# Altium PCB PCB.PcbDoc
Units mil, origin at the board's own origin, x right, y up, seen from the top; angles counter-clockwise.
Board outline 2165.35 x 1771.65 mil, 4 copper layers (Top Layer, VCC, GND, Bottom Layer), stack 25.634 mil thick; 104 components, 82 nets, 409 pads, 177 vias.
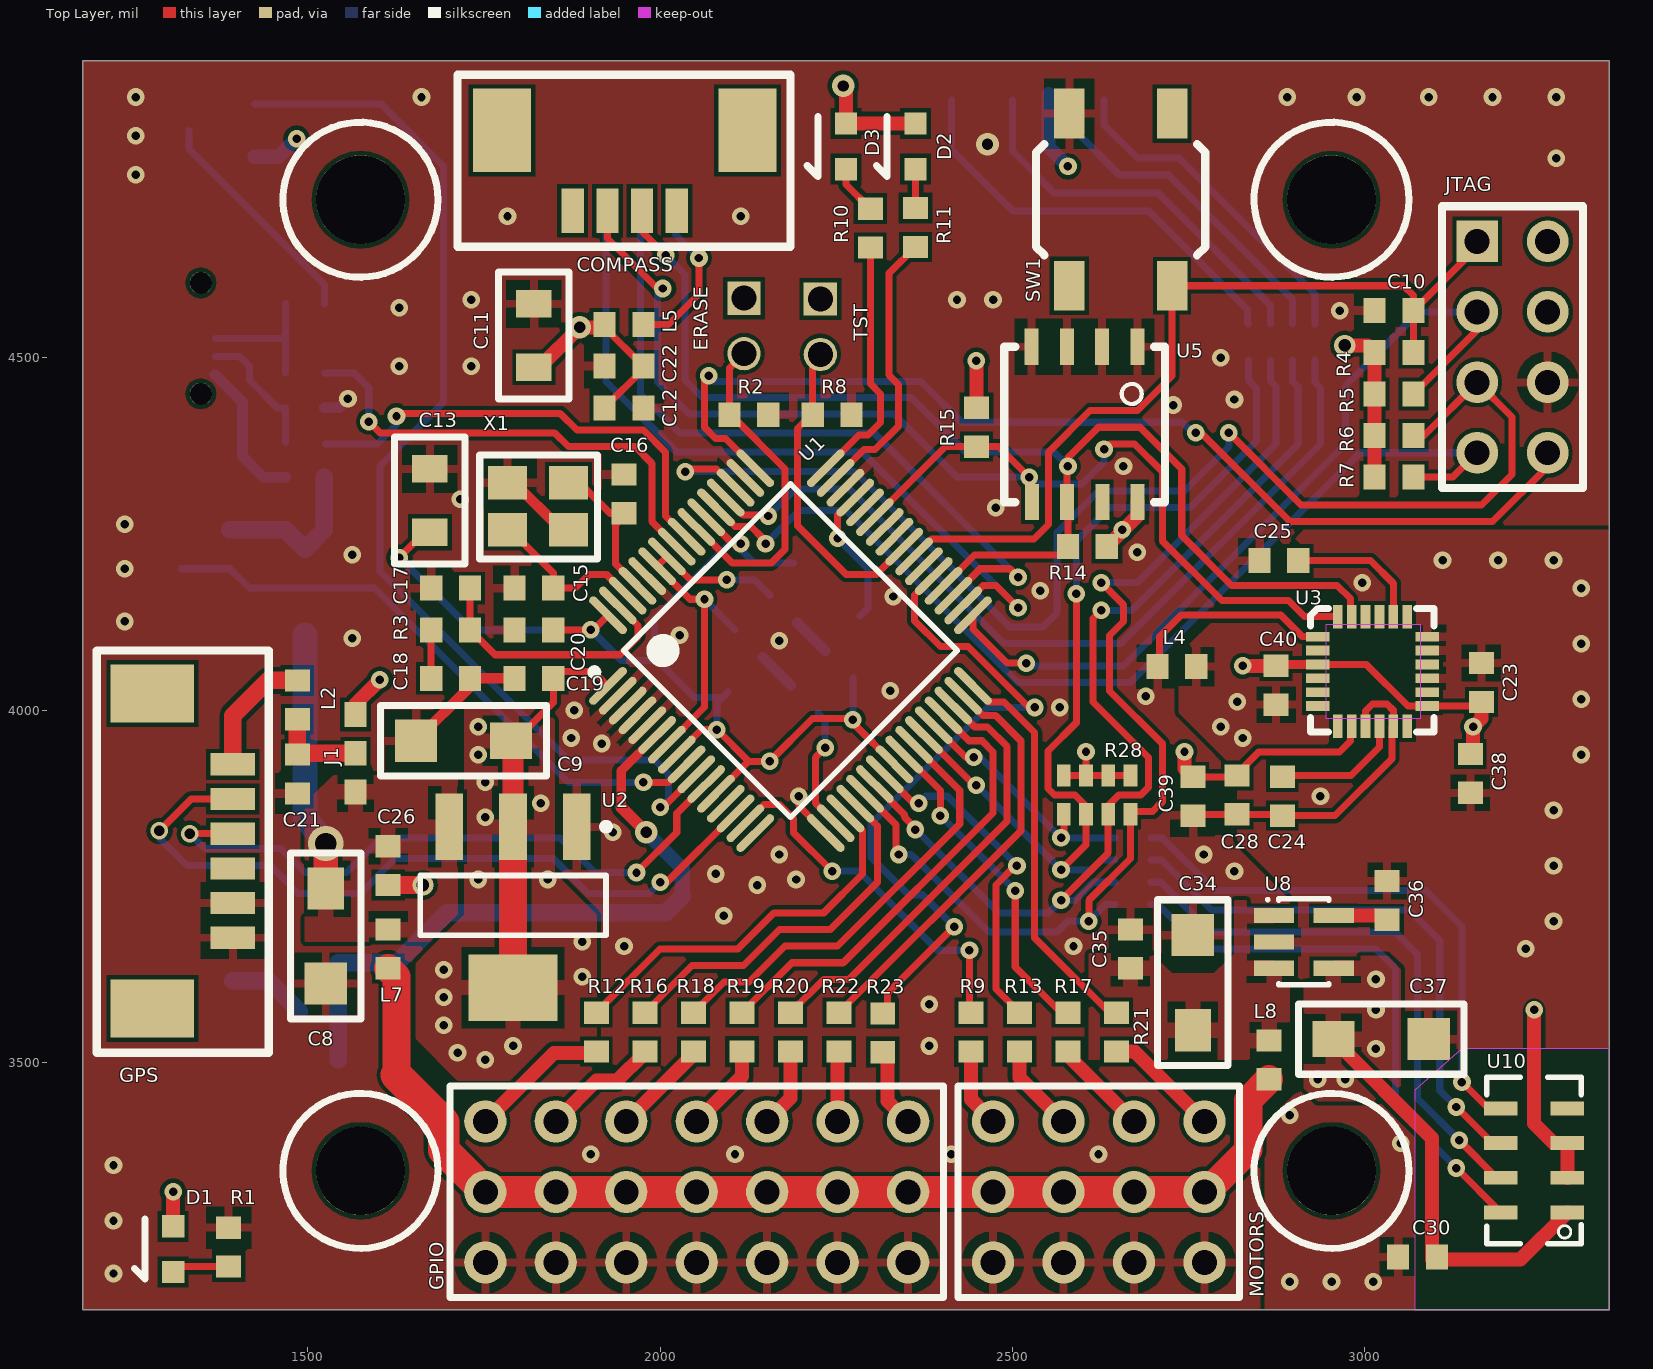
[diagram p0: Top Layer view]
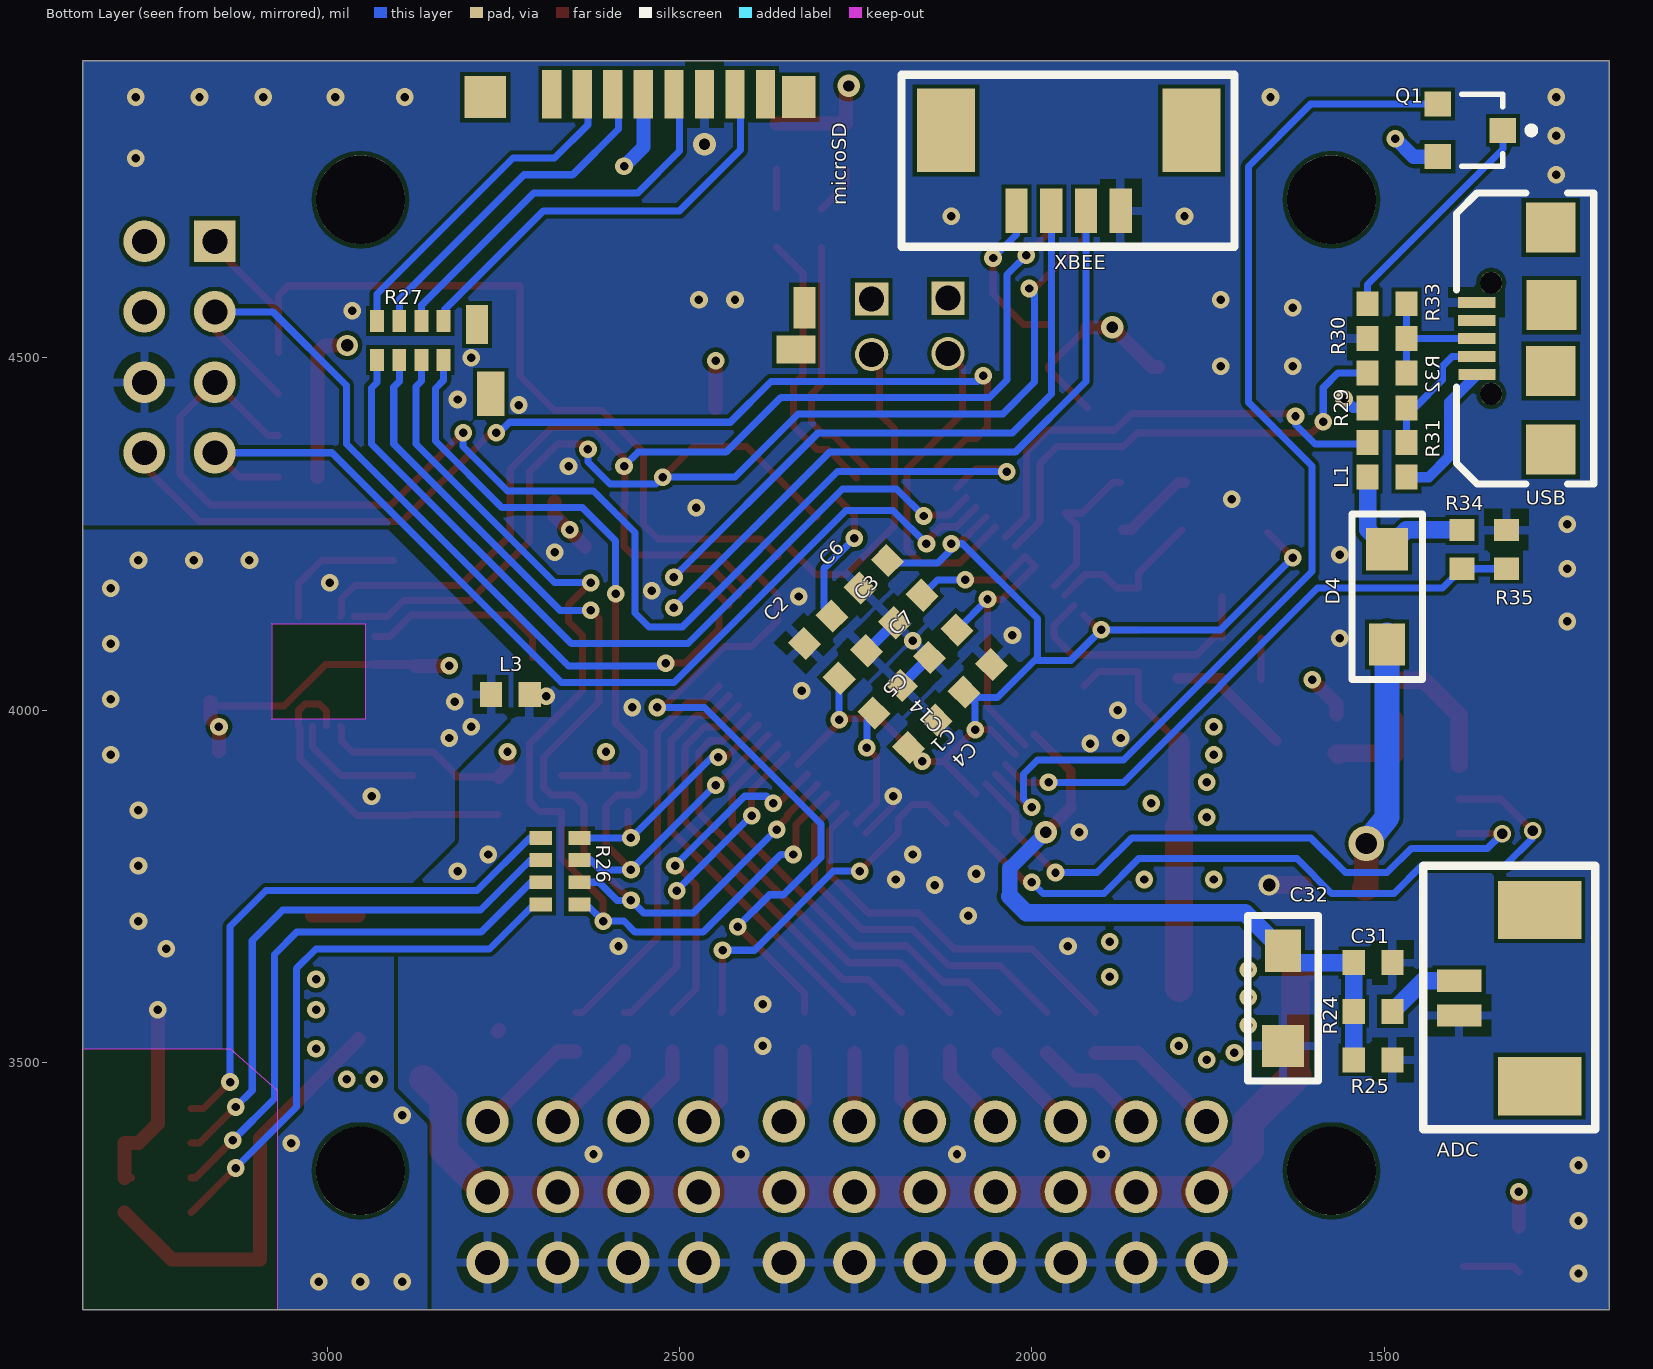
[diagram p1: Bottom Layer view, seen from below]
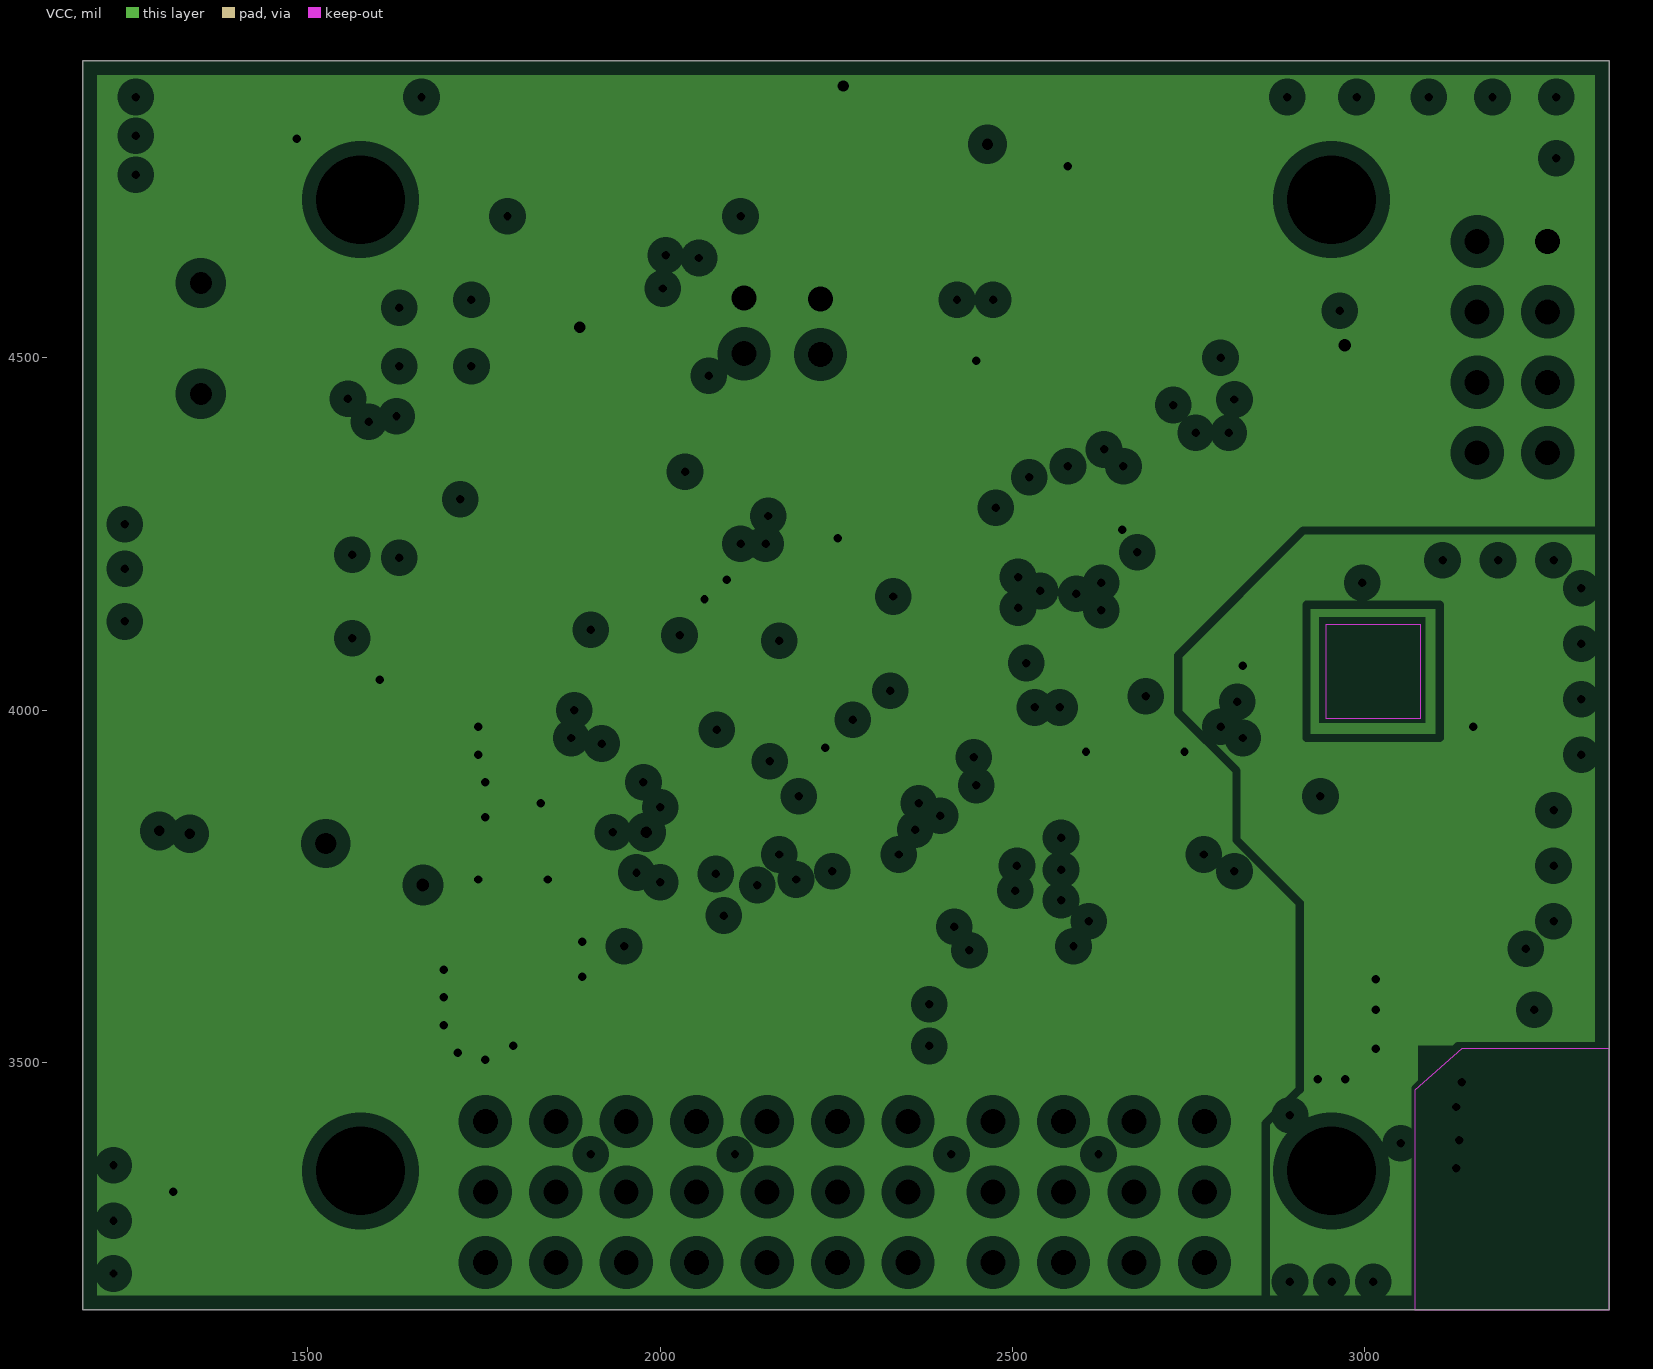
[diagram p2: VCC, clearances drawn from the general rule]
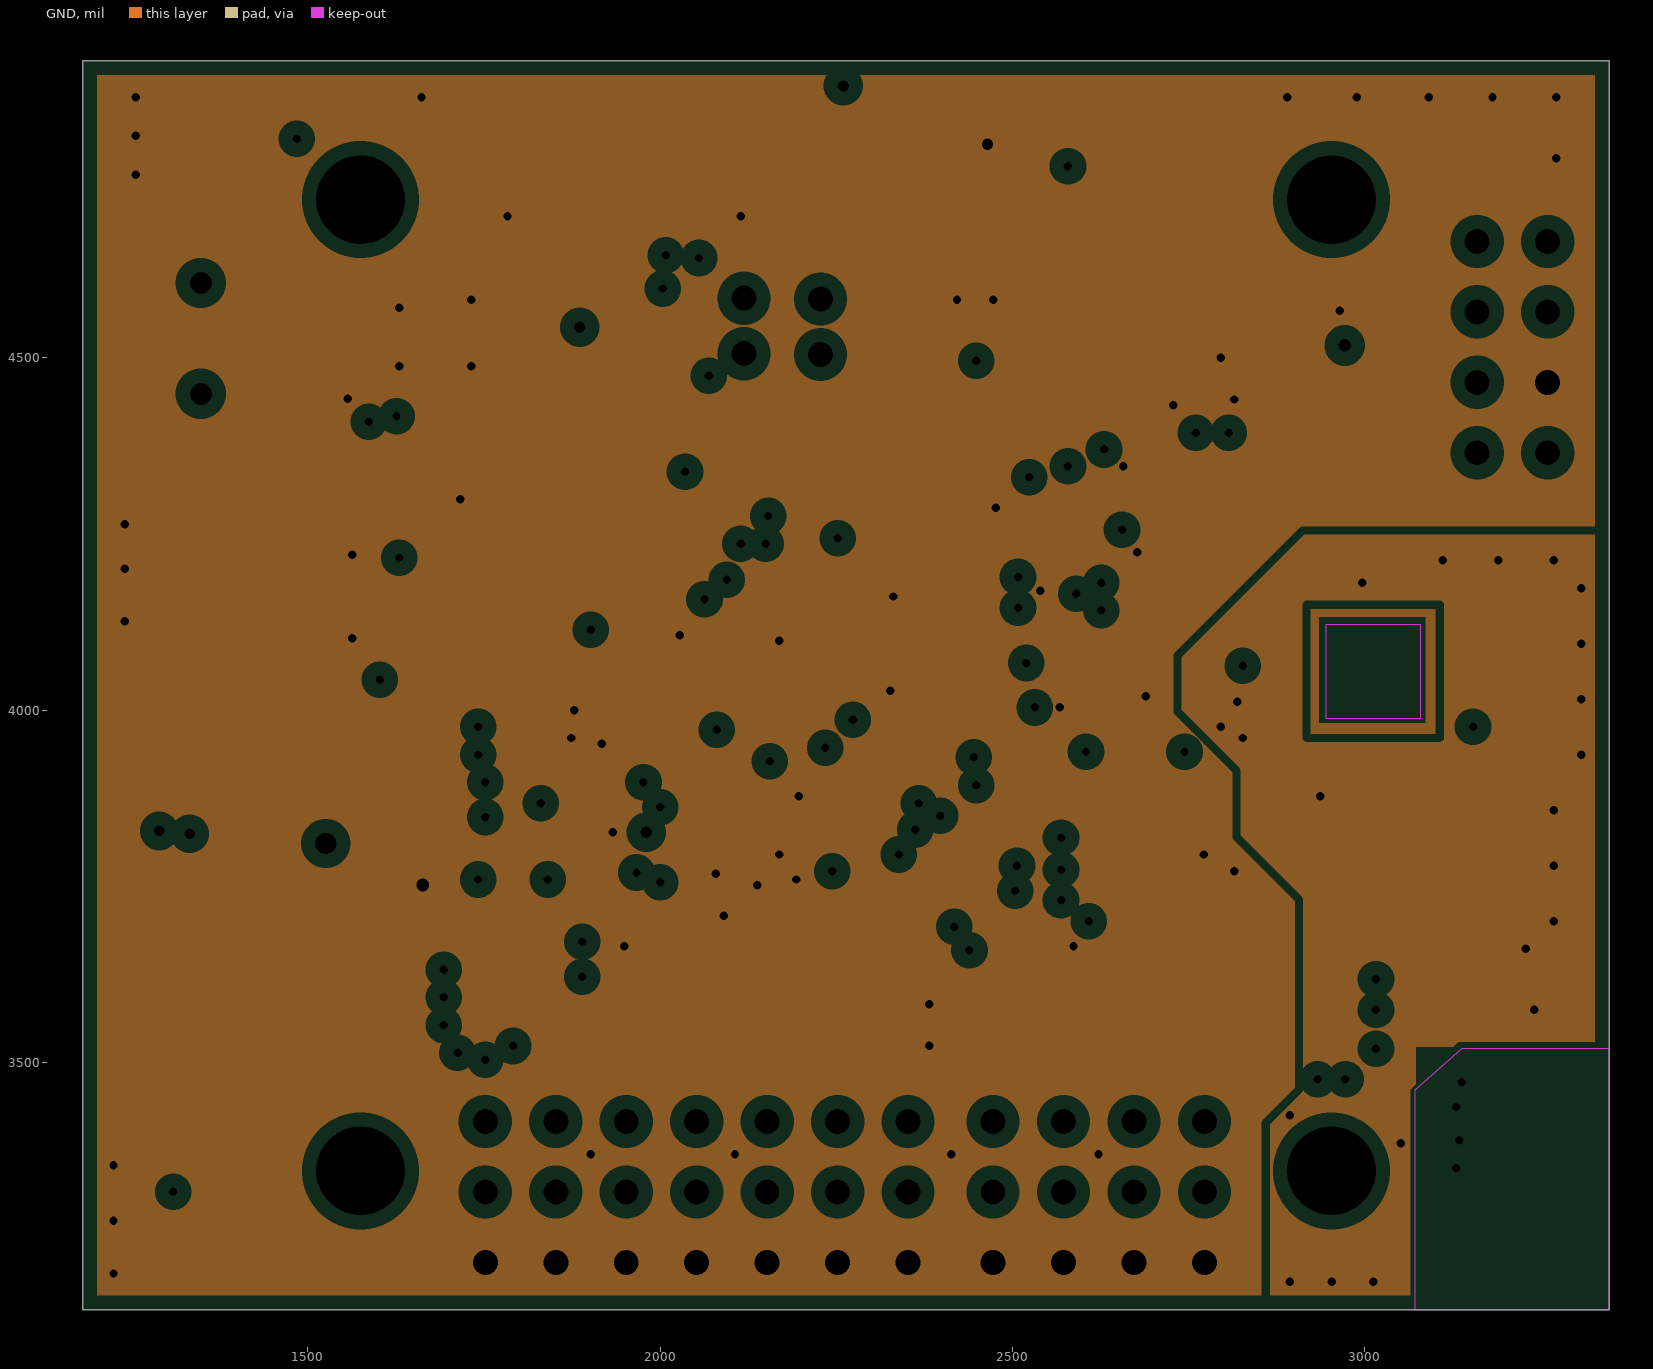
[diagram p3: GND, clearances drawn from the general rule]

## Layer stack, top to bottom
Top Solder: solder mask 0.4, Solder Resist, Dk 3.5
Top Layer: signal copper 1.4
Dielectric 1: core 5, FR-4, Dk 4.2
VCC: plane copper 1.417, net (Multiple Nets)
Dielectric 3: prepreg 5, Dk 4.2
GND: plane copper 1.417, net (Multiple Nets)
Dielectric 2: core 10, Dk 4.2
Bottom Layer: signal copper 1.4
Bottom Solder: solder mask 0.4, Solder Resist, Dk 3.5

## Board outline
1181.1,3149.61 3346.46,3149.61 3346.46,4921.26 1181.1,4921.26

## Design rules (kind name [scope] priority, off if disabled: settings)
Clearance [All] p1: gap=5.91
PlaneClearance [All] p1: clearance=20
PlaneConnect [All] p1: planeconnectstyle=Relief reliefexpansion=20 reliefentries=4 reliefconductorwidth=22 reliefairgap=10
PolygonConnect Via [IsVia] p1: connectstyle=Direct reliefconductorwidth=10 reliefentries=4 polygonreliefangle="90 Angle" airgapwidth=10
PolygonConnect Track [IsTrack] p2: connectstyle=Direct reliefconductorwidth=10 reliefentries=4 polygonreliefangle="90 Angle" airgapwidth=10
PolygonConnect GND [InNet('GND')] p3: connectstyle=Relief reliefconductorwidth=12 reliefentries=4 polygonreliefangle="90 Angle" airgapwidth=14
PolygonConnect AGND [InNet('AGND')] p4: connectstyle=Relief reliefconductorwidth=12 reliefentries=4 polygonreliefangle="90 Angle" airgapwidth=10
PolygonConnect A3V3 [InNet('A3V3')] p5: connectstyle=Relief reliefconductorwidth=22 reliefentries=4 polygonreliefangle="90 Angle" airgapwidth=10
PolygonConnect 5Vb [All] p6: connectstyle=Relief reliefconductorwidth=22 reliefentries=4 polygonreliefangle="90 Angle" airgapwidth=10
PolygonConnect 5Va [InNet('5VA')] p7: connectstyle=Relief reliefconductorwidth=22 reliefentries=4 polygonreliefangle="90 Angle" airgapwidth=10
PolygonConnect 3.3V [InNet('3.3V')] p8: connectstyle=Relief reliefconductorwidth=22 reliefentries=4 polygonreliefangle="90 Angle" airgapwidth=10
RoutingVias [All] p1: holewidth=28 width=50 viastyle="Through Hole" minholewidth=28 minwidth=50 maxholewidth=28 maxwidth=50
SolderMaskExpansion [All] p1: expansion=4
Width [All] p1: maxlimit=100 minlimit=10 preferedwidth=10
27 further rules are at their usual default settings.

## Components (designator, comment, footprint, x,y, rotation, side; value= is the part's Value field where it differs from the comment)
ADC "AD_Port" 2P_1.25mm（贴片） 1220.47,3425.2 r90 bottom
C1 "0.1u" 1608[0603] 2204.72,4015.75 r315 bottom
C2 "0.1u" 1608[0603] 2303.15,4114.17 r135 bottom
C3 "0.1u" 1608[0603] 2175.2,4143.7 r135 bottom
C4 "0.1u" 1608[0603] 2155.51,3966.54 r315 bottom
C5 "0.1u" 1608[0603] 2253.94,4064.96 r315 bottom
C6 "0.1u" 1608[0603] 2224.41,4192.91 r135 bottom
C7 "0.1u" 1608[0603] 2125.98,4094.49 r135 bottom
C8 "10u" 1206 1525.59,3612.2 r90 top
C9 "10u" 1206 1653.54,3956.69 r0 top
C10 "0.01u" 1608[0603] 3041.34,4566.93 r0 top
C11 "2.2u" 0805 1820.87,4576.77 r270 top
C12 "1n" 1608[0603] 1948.82,4429.13 r180 top
C13 "4.7u" 0805 1673.23,4342.52 r270 top
C14 "0.1u" 1608[0603] 2076.77,4045.28 r315 bottom
C15 "8p" 1608[0603] 1820.87,4173.23 r0 top
C16 "8p" 1608[0603] 1948.82,4307.09 r270 top
C17 "1n" 1608[0603] 1702.76,4173.23 r0 top
C18 "10n" 1608[0603] 1702.76,4045.28 r180 top
C19 "0.1u" 1608[0603] 1820.87,4045.28 r0 top
C20 "0.1u" 1608[0603] 1820.87,4114.17 r0 top
C21 "1u" 1608[0603] 1485.24,3909.45 r90 top
C22 "1u" 1608[0603] 1948.82,4488.19 r0 top
C23 "0.1u" 1608[0603] 3165.35,4039.37 r270 top
C24 "0.1u" 1608[0603] 2882.87,3877.95 r90 top
C25 "2.2n" 1608[0603] 2877.95,4212.6 r0 top
C26 "0.1u" 1608[0603] 1614.17,3779.53 r90 top
C28 "10n" 1608[0603] 2818.9,3879.92 r90 top
C30 "0.1u" 1608[0603] 3074.8,3224.41 r0 top
C31 "0.1u" 1608[0603] 1515.75,3641.73 r0 bottom
C32 "10u" 1206 1643.7,3523.62 r90 bottom
C34 "10u" 1206 2755.91,3681.1 r270 top
C35 "0.1u" 1608[0603] 2667.32,3661.42 r270 top
C36 "470p" 1608[0603] 3031.5,3730.32 r270 top
C37 "10u" 1206 3090.55,3533.46 r180 top
C38 "2.2u" 1608[0603] 3149.61,3910.43 r90 top
C39 "1u" 1608[0603] 2755.91,3877.95 r90 top
C40 "0.1u" 1608[0603] 2874.02,4035.43 r90 top
COMPASS "COMPASS" 4P_1.25mm（贴片） 2165.35,4881.89 r180 top
D1 "LED" LED 1309.06,3267.72 r270 top
D2 "LED" LED 2263.78,4832.68 r270 top
D3 "LED" LED 2362.2,4832.68 r270 top
D4 "Diode" 1206 1496.06,4228.35 r270 bottom
ERASE "MHDR1X2" PIN2mm*2 2119.09,4584.65 r270 top
GPIO "3*7 PWMin" HEADER3X7 1751.97,3216.54 r0 top
GPS "GPS" 6P_PH1.25mm（贴片） 1220.47,4064.96 r270 top
J1 "0603Jumper" 1-2Jumper 1567.91,3938.98 r270 top
JTAG "JTAG" JTAG2 3159.45,4665.35 r0 top
L1 "Ferrite" 1608[0603] 1496.06,4330.71 r0 bottom
L2 "Ferrite" 1608[0603] 1485.24,4014.76 r270 top
L3 "Ferrite" 1608[0603] 2740.16,4022.64 r0 bottom
L4 "Ferrite" 1608[0603] 2733.27,4062.01 r0 top
L5 "Ferrite" 1608[0603] 1948.82,4547.24 r180 top
L7 "" 1608[0603] 1614.17,3661.42 r90 top
L8 "" 1608[0603] 2864.17,3503.94 r90 top
microSD "SD Connector" SD_Connector 2377.95,4838.58 r0 bottom
MOTORS "3*4P PWMout" header3x4 2472.44,3216.54 r0 top
Q1 "ZXM61P02F" SOT23 1377.95,4822.83 r270 bottom
R1 "1K" 1608[0603] 1387.8,3238.19 r270 top
R2 "10K" 1608[0603] 2125.98,4419.29 r180 top
R3 "1.5K" 1608[0603] 1702.76,4114.17 r0 top
R4 "47K" 1608[0603] 3041.34,4507.87 r180 top
R5 "10K" 1608[0603] 3041.34,4448.82 r180 top
R6 "10K" 1608[0603] 3041.34,4389.76 r180 top
R7 "10K" 1608[0603] 3041.34,4330.71 r180 top
R8 "10K" 1608[0603] 2244.09,4419.29 r180 top
R9 "1K" 1608[0603] 2440.94,3543.31 r270 top
R10 "270R" 1608[0603] 2298.23,4684.06 r90 top
R11 "270R" 1608[0603] 2362.2,4685.04 r90 top
R12 "220" 1608[0603] 1909.45,3543.31 r270 top
R13 "1K" 1608[0603] 2509.84,3543.31 r270 top
R14 "47K" 1608[0603] 2606.3,4232.28 r180 top
R15 "47K" 1608[0603] 2448.82,4401.57 r270 top
R16 "220" 1608[0603] 1978.35,3543.31 r270 top
R17 "1K" 1608[0603] 2578.74,3543.31 r270 top
R18 "220" 1608[0603] 2047.24,3543.31 r270 top
R19 "220" 1608[0603] 2116.14,3543.31 r270 top
R20 "220" 1608[0603] 2185.04,3543.31 r270 top
R21 "1K" 1608[0603] 2647.64,3543.31 r270 top
R22 "220" 1608[0603] 2253.94,3543.31 r270 top
R23 "220" 1608[0603] 2315.94,3542.32 r270 top
R24 "200K" 1608[0603] 1515.75,3572.83 r180 bottom
R25 "470K" 1608[0603] 1515.75,3503.94 r0 bottom
R26 "100R*4" Resistances 2696.85,3818.9 r270 bottom
R27 "100R*4" Resistances 2929.13,4497.05 r180 bottom
R28 "47K*4" Resistances 2667.32,3907.48 r180 top
R29 "330K" 1608[0603] 1496.06,4429.13 r0 bottom
R30 "330K" 1608[0603] 1496.06,4527.56 r0 bottom
R31 "22R" 1608[0603] 1496.06,4379.92 r0 bottom
R32 "22R" 1608[0603] 1496.06,4478.35 r0 bottom
R33 "1.5K" 1608[0603] 1496.06,4576.77 r180 bottom
R34 "27K" 1608[0603] 1389.76,4228.35 r270 bottom
R35 "47K" 1608[0603] 1326.77,4228.35 r270 bottom
SW1 "Push Button" switch 2746.06,4566.93 r90 top
TST "MHDR1X2" PIN2mm*2 2227.36,4583.66 r270 top
U1 "AT91SAM7S256-AU-001" LQFP64_N 2185.04,4084.65 r45 top
U2 "LM1117N33" SOT230P700X180-4N 1791.34,3720.47 r270 top
U3 "MPU9150" LGANEW 2933.07,4104.33 r0 top
U5 "EEPROM" EEPROM 2677.17,4515.75 r180 top
U8 "MIC5207LE33" S5 2913.39,3671.26 r270 top
U10 "MS5611" MS_5611 3287.4,3287.4 r180 top
USB "USB_Receptacle" micro_usb 1348.43,4606.3 r0 bottom
X1 "" OSC2 1783.46,4322.83 r0 top
XBEE "XBEE" 4P_1.25mm（贴片） 1732.28,4881.89 r0 bottom

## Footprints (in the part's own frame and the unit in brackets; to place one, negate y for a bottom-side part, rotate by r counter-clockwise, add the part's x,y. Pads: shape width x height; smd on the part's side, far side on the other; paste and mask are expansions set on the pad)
1-2Jumper [mm]
  rect 0.9x0.8 smd: 1(0,0) 2(1.4,0) 3(-1.4,0)
2P_1.25mm（贴片） [mm]
  rect 2.1x3 smd: 0(1.05,1.5) 5(7.4,1.5)
  rect 0.8x1.6 smd: 1(4.85,4.4) 2(3.6,4.4)
  silkscreen extent -0.5,-0.5 9,5.7
4P_1.25mm（贴片） [mm]
  rect 2.1x3 smd: 0(1.05,1.5) 5(9.9,1.5)
  rect 0.8x1.6 smd: 1(7.35,4.4) 2(6.1,4.4) 3(4.85,4.4) 4(3.6,4.4)
  silkscreen extent -0.5,-0.5 11.5,5.7
6P_PH1.25mm（贴片） [mm]
  rect 2.1x3 smd: 0(1.05,1.5) 7(12.4,1.5)
  rect 0.8x1.6 smd: 1(3.6,4.4) 2(4.85,4.4) 3(6.1,4.4) 4(8.6,4.4) 4(9.85,4.4) 5(7.35,4.4)
  silkscreen extent -0.5,-0.5 14,5.7
0805 [mm]
  rect 1x1.27 smd: 1(0,0) 2(2.286,0)
  silkscreen extent -1.14,-1.27 3.43,1.27
1206 [mil]
  rect 60x60 smd: 1(0,0)
  rect 60x51.18 smd: 2(135,0)
  silkscreen extent -50,-50 185,50
1608[0603] [mm] "Chip Capacitor, Body 1.6x0.8mm, IPC High Density"
  rect 0.8x0.9 smd: 1(-0.7,0) 2(0.7,0)
  body extent -0.87,-0.47 0.87,0.47, height 1.3
EEPROM [mm]
  rect 0.5x1.3 smd: 1(0,0) 2(1.27,0) 3(2.54,0) 4(3.81,0) 5(3.8,5.6) 6(2.53,5.6) 7(1.26,5.6) 8(-0.01,5.6)
  silkscreen extent -1,0 4.8,5.6
header3x4 [mil]
  round 60 hole 35.43: 1(0,0) 2(0,100) 3(0,200) 4(100,0) 5(100,100) 6(100,200) 7(200,0) 8(200,100) 9(200,200) 10(300,0) 11(300,100) 12(300,200)
  silkscreen extent -50,-50 350,250
HEADER3X7 [mil]
  round 60 hole 35.43: 1(0,0) 2(0,100) 3(0,200) 4(100,0) 5(100,100) 6(100,200) 7(200,0) 8(200,100) 9(200,200) 10(300,0) 11(300,100) 12(300,200) 13(400,0) 14(400,100) 15(400,200) 16(500,0) 17(500,100) 18(500,200) 19(600,0) 20(600,100) 21(600,200)
  silkscreen extent -50,-50 650,250
JTAG2 [mm]
  rect 1.5x1.5 hole 0.9: 1(0,0)
  round 1.5 hole 0.9: 2(0,-2.54) 3(0,-5.08) 4(0,-7.62) 5(2.54,0) 6(2.54,-2.54) 7(2.54,-5.08) 8(2.54,-7.62)
  silkscreen extent -1.27,-8.89 3.81,1.27
LED [mm]
  rect 0.8x0.8 smd: 1(0,0) 2(1.65,0)
  silkscreen extent -0.25,-1.4 1.9,-1.02
LGANEW [mm]
  rect 0.85x0.35 smd mask+0: 1(0,0) 2(0,-0.5) 3(0,-1) 4(0,-1.5) 5(0,-2) 6(0,-2.5) 13(3.95,-2.5) 14(3.95,-2) 15(3.95,-1.5) 16(3.95,-1) 17(3.95,-0.5) 18(3.95,0)
  rect 0.35x0.85 smd mask+0: 7(0.725,-3.225) 8(1.225,-3.225) 9(1.725,-3.225) 10(2.225,-3.225) 11(2.725,-3.225) 12(3.225,-3.225) 19(3.225,0.725) 20(2.725,0.725) 21(2.225,0.725) 22(1.725,0.725) 23(1.225,0.725) 24(0.725,0.725)
  silkscreen extent -0.25,-3.43 4.19,1.02
LQFP64_N [mm] "Thin QFP, 64-Leads, Body 10x10mm, Pitch 0.5mm, IPC Medium Density"
  oval 1.8x0.3 smd: 1(-5.55,3.75) 2(-5.55,3.25) 3(-5.55,2.75) 4(-5.55,2.25) 5(-5.55,1.75) 6(-5.55,1.25) 7(-5.55,0.75) 8(-5.55,0.25) 9(-5.55,-0.25) 10(-5.55,-0.75) 11(-5.55,-1.25) 12(-5.55,-1.75) 13(-5.55,-2.25) 14(-5.55,-2.75) 15(-5.55,-3.25) 16(-5.55,-3.75) 33(5.55,-3.75) 34(5.55,-3.25) 35(5.55,-2.75) 36(5.55,-2.25) 37(5.55,-1.75) 38(5.55,-1.25) 39(5.55,-0.75) 40(5.55,-0.25) 41(5.55,0.25) 42(5.55,0.75) 43(5.55,1.25) 44(5.55,1.75) 45(5.55,2.25) 46(5.55,2.75) 47(5.55,3.25) 48(5.55,3.75)
  oval 0.3x1.8 smd: 17(-3.75,-5.55) 18(-3.25,-5.55) 19(-2.75,-5.55) 20(-2.25,-5.55) 21(-1.75,-5.55) 22(-1.25,-5.55) 23(-0.75,-5.55) 24(-0.25,-5.55) 25(0.25,-5.55) 26(0.75,-5.55) 27(1.25,-5.55) 28(1.75,-5.55) 29(2.25,-5.55) 30(2.75,-5.55) 31(3.25,-5.55) 32(3.75,-5.55) 49(3.75,5.55) 50(3.25,5.55) 51(2.75,5.55) 52(2.25,5.55) 53(1.75,5.55) 54(1.25,5.55) 55(0.75,5.55) 56(0.25,5.55) 57(-0.25,5.55) 58(-0.75,5.55) 59(-1.25,5.55) 60(-1.75,5.55) 61(-2.25,5.55) 62(-2.75,5.55) 63(-3.25,5.55) 64(-3.75,5.55)
  silkscreen extent -5.67,-4.25 4.25,4.57, body extent -5,-5 5,5, height 1.6
micro_usb [mm]
  rect 1.35x0.4 smd: 1(0.508,3.302) 2(0.525,2.65) 3(0.525,2) 4(0.525,1.35) 5(0.525,0.7)
  rect 1.8x1.8 smd: 6(-2.175,0.8) 6(-2.15,-2) 6(-2.15,3.175) 6(-2.15,6)
  round 0.8 hole 0.8: 18(0,0) 19(0,4)
  silkscreen extent -3.7,-3.25 1.25,7.25
MS_5611 [mm]
  rect 1.2x0.5 smd: 1(0,0) 2(0,-1.25) 3(0,-2.5) 4(0,-3.75) 5(2.4,-3.75) 6(2.4,-2.5) 7(2.4,-1.25) 8(2.4,0)
  silkscreen extent -0.5,-4.88 2.9,1.13
OSC2 [mm]
  rect 1.4x1.2 smd: 1(0,-1.7) 2(2.2,-1.7) 3(2.2,0) 4(0,0)
  silkscreen extent -1,-2.75 3.25,1
PIN2mm*2 [mm]
  rect 1.2x1.2 hole 0.9: 1(0,0)
  round 1.2 hole 0.9: 2(2,0)
Resistances [mm]
  rect 0.5x0.8 smd: 1(0,0) 2(0.8,0) 3(1.6,0) 4(2.4,0) 5(2.4,1.4) 6(1.6,1.4) 7(0.8,1.4) 8(0,1.4)
S5 [mm] "SOT-23/SC-74A; 5 Leads; Body 3.1 x 3 mm, inc. leads (LxW max)"
  rect 0.55x1.45 smd: 1(-0.95,-1.075) 2(0,-1.075) 3(0.95,-1.075) 4(0.95,1.075) 5(-0.95,1.075)
  silkscreen extent -1.57,-1.35 1.55,0.9
SD_Connector [mm]
  rect 0.7x1.75 smd: 1(6.6,-0.9) 2(5.5,-0.9) 3(4.4,-0.9) 4(3.3,-0.9) 5(2.2,-0.9) 6(1.1,-0.9) 7(0,-0.9) 7(7.7,-0.9)
  rect 0.8x1.5 smd: 7(-1.4,6.8)
  rect 1.2x1.5 smd: 7(-1.2,-0.8)
  rect 1.4x1 smd: 7(-1.1,8.3)
  rect 1x1.6 smd: 7(9.9,9.9)
  rect 1.5x1.5 smd: 7(10.1,-0.8)
  rect 0.8x1.4 smd: 7(10.4,7.4)
SOT23 [mm] "SOT-23; 3 Leads; Body 3.1 x 2.5 mm, inc. leads (LxW max), Alternate Lead Configuration"
  rect 0.9x0.95 smd: 1(0,1.175) 2(0.95,-1.175) 3(-0.95,-1.175)
  silkscreen extent -1.3,-0.3 1.3,2.32
SOT230P700X180-4N [mm] "SOT223, 4-Leads, Body 6.50x7.00mm (avg), Pitch 2.30mm, IPC Medium Density"
  rect 2.4x1 smd: 1(-2.9,2.3) 2(-2.9,0) 3(-2.9,-2.3)
  rect 2.4x3.2 smd: 4(2.9,0)
  silkscreen extent -3.02,-3.35 1.02,3.48, body extent -1.85,-3.35 1.85,3.35, height 1.8
switch [mm]
  rect 1.8x1.1 smd: 1(0.9,4.2) 2(7.1,4.2) 3(0.9,0.5) 4(7.1,0.5)
  silkscreen extent 2,-0.7 6,5.4

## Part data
C1 C2 C3 C4 C5 C6 C7 C10 C12 C14 C15 C16 C17 C18 C19 C20 C21 C22 C23 C24 C25 C28 C30 C31 C35 C36 C37 C38 C39 C40: library part "Cap 0603", "0603 Capacitor"
C8 C9 C26 C32 C34: library part "Cap 1206", "1206 Capacitor"
C11 C13: library part "Cap 0805", "0805 Capacitor"
COMPASS GPS XBEE: "Header, 4-Pin"
D1 D2 D3: "Typical RED, GREEN, YELLOW, AMBER GaAs LED"
D4: "Default Diode"
ERASE TST: "Header, 2-Pin"
GPIO: library part MyPWMin
JTAG: library part JTAG2
L1 L3 L4 L7 L8: library part Inductor, "Inductor"
MOTORS: library part MyPWMout
Q1: "20V P-Channel Enhancement Mode MOSFET"
R1 R2 R3 R4 R5 R6 R7 R8 R9 R10 R11 R12 R13 R14 R15 R16 R17 R18 R19 R20 R21 R22 R23 R24 R25 R29 R30 R31 R32 R33 R34 R35: library part "Res 0603", "Resistor"
R26 R27 R28: library part "Res Pack4", "Isolated Resistor Network"
U1: "AT91 ARM Thumb-based 32-bit Microcontroller, 256KB Flash, 64KB SRAM, 64-Pin LQFP, 11-ch. PDC, Industrial Grade (-40癈 to 85癈), Pb-Free"
U2: library part LM1117S33, "3.3V Regulator"
U5: library part ROM
U8: library part MIC5207
X1: library part OSC2

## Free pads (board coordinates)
  round 125.98 hole 125.98: 0(1574.8,3346.46) 1(2952.76,3346.46) 2(2952.76,4724.41) 3(1574.8,4724.41)

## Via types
v1: diameter 25, hole 12, Top Layer to Bottom Layer, 168 vias
v2: diameter 32, hole 16, Top Layer to Bottom Layer, 4 vias
v3: diameter 30, hole 18, Top Layer to Bottom Layer, 2 vias
v4: diameter 25, hole 15, Top Layer to Bottom Layer, 2 vias
v5: diameter 50, hole 30, Top Layer to Bottom Layer, 1 vias

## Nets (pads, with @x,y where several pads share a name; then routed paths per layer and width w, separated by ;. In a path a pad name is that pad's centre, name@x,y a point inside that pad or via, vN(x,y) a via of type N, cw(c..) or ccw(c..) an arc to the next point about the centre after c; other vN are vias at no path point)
3.3V: C1.2 C2.2 C3.2 C7.2 C9.2 C11.2 C12.2 C19.2 C22.2 C28.2 C39.2 D1.1 D2.1 D3.1 ERASE.1 J1.3 JTAG.5 L5.2 microSD.3 Q1.2 R4.2 R5.2 R6.2 R7.2 R14.1 R15.1 R28.1 R28.2 R28.3 R28.4 TST.1 U1.1 U1.7 U1.18 U1.45 U1.58 U1.59 U2.2 U2.4 U3.8 U5.8 | length 3042.7
  Top Layer w10: C9.2@1791.34,3953.9 1848.43,4010.99 1848.43,4055.12 1905.56,4055.12 U1.1 ; C12.2 1976.38,4484.25 C22.2 L5.2@1921.26,4543.31 ; U1.7 2062.99,4004.36 v1(2062.99,4157.48) 2042.61,4157.48 U1.59 U1.58 2042.89,4185.04 v1(2094.49,4185.04) ; v1(2234.25,3946.85) 2220.62,3933.22 2220.62,3868.11 U1.18 ; v1(2251.97,4244.09) 2251.97,4276.85 U1.45 ; R28.4 R28.3 ; v1(2604.33,3940.94) R28.3 ; R28.1 R28.2 R28.3 ; C39.2 C28.2@2816.93,3905.51 ; C28.2 2818.9,3910.43 2849.41,3940.94 2964.24,3940.94 2979.41,3956.11 2979.41,3975.47 U3.8
  Top Layer w20: D1.1 v1(1309.06,3316.93) ; J1.3 1567.91,4008.86 v1(1602.36,4043.31) ; C11.2 1829.29,4486.77 v2(1885.83,4543.31) L5.2@1921.26,4543.31 ; v2(2259.84,4885.83) 2263.78,4881.89 D2.1 D3.1 ; R15.1 v1(2448.82,4496.06) ; R14.1 2677.56,4275.99 U5.8 ; v1(2744.09,3940.94) 2744.09,3917.32 C39.2 ; v3(2971.46,4517.72) 3003.94,4517.72 R4.2 R5.2 R6.2 R7.2
  Top Layer w30: U2.2 C9.2@1791.34,3953.9
  Top Layer w40: U2.4 U2.2
  Bottom Layer w10: v1(2062.99,4157.48) C7.2 ; v1(2094.49,4185.04) 2133.86,4185.04 C3.2 ; C1.2 2234.25,3986.22 v1(2234.25,3946.85) ; v1(2251.97,4244.09) 2295.28,4200.79 2295.28,4145.27 C2.2
  Bottom Layer w20: Q1.2 1458.66,4785.43 v1(1484.25,4811.02) ; microSD.3 2551.18,4799.21 v1(2578.74,4771.65)
  other v1: 1751.97,3503.94 1712.6,3513.78 1791.34,3523.62 1692.91,3553.15 1692.91,3592.52 1889.76,3622.05 1692.91,3631.89 1889.76,3671.26 1742.13,3759.84 1840.55,3759.84 1751.97,3848.43 1830.71,3868.11 1751.97,3897.64 1742.13,3937.01 1742.13,3976.38 2655.51,4255.91
5VA: C34.2 C35.2 L8.2 U8.1 U8.3 | length 2.8
  Top Layer w20: C34.2 C34.2@2757.87,3544.13
5VB: C8.2 C26.2 D4.2 J1.2 L7.2 U2.3 | length 373
  Top Layer w35: v5(1525.59,3811.02) C8.2 C8.2@1528.39,3747.2
  Bottom Layer w35: D4.2@1496.06,4107.13 D4.2 1496.06,3848.43 v5(1525.59,3811.02)
A3V3: C23.2 C30.2 C37.2 C38.2 C40.2 U3.3 U3.13 U8.4 U10.1 | length 1023.5
  Top Layer w10: C40.2 C40.2@2875.98,4064.96 ; U3.3 3001.97,4064.96 3061.02,4005.9 U3.13 C23.2@3159.45,4005.9
  Top Layer w13: C40.2@2875.98,4064.96 U3.3
  Top Layer w20: v1(2826.77,4062.99) C40.2 ; C37.2@2955.71,3533.62 C37.2 2955.55,3532.64 3095.47,3392.72 3095.47,3220.47 3220.47,3220.47 U10.1 ; C38.2@3153.54,3941.93 v1(3153.54,3976.38) 3165.35,3988.19 C23.2
  other v1: 2933.07,3476.38 2972.44,3476.38 3015.75,3519.68 3015.75,3574.8 3015.75,3618.11
AD7: C31.2 C32.2 R24.1 R25.2 U1.6 | length 950.8
  Top Layer w12: 1944.88,3914.09 U1.6
  Top Layer w14: 1944.88,3862.2 1944.88,3914.09
  Top Layer w17: 1944.88,3862.2 v2(1980.32,3826.77)
  Bottom Layer w20: v2(1980.32,3826.77) 2031.5,3775.59
  Bottom Layer w22: 2031.5,3736.22 2031.5,3775.59
  Bottom Layer w25: R25.2 R24.1 C31.2 1626.81,3641.73 C32.2 1697.68,3712.6 2007.87,3712.6 2031.5,3736.22
"AD PORT": ADC.1 R24.2 | length 112.4
  Bottom Layer w25: ADC.1 1444.88,3616.14 R24.2
AGND: C23.1 C30.1 C36.1 C37.1 C38.1 C40.1 L3.2 L4.2 U3.15 U3.17 U3.18 U8.2 U10.2 U10.3 | length 279.1
  Top Layer w10: U10.2@3277.56,3336.61 U10.2
  Top Layer w20: v1(3240.16,3574.8) 3240.16,3413.39 3267.72,3385.83 U10.3 U10.2
  other v1: 2893.7,3188.98 2952.76,3188.98 3011.81,3188.98 3051.18,3385.83 2893.7,3425.2 3228.35,3661.42 3267.72,3700.79 3267.72,3779.53 3267.72,3858.27 2937.01,3877.95 3307.09,3937.01 2826.77,3960.63 2795.28,3976.38 2818.9,4011.81 3307.09,4015.75 3307.09,4094.49 3307.09,4173.23 2996.06,4181.1 3110.24,4212.6 3188.98,4212.6 3267.72,4212.6
CS0: R26.8 R28.5 U1.28 | length 362.7
  Top Layer w10: U1.28 2434.05,3933.07 v1(2444.88,3933.07) ; v1(2568.9,3818.9) 2572.83,3822.83 R28.5@2572.83,3856.3
  Bottom Layer w10: v1(2444.88,3933.07) 2454.72,3933.07 v1(2568.9,3818.9) R26.8@2645.67,3818.9
CS1: R27.1 U1.52 | length 1201.3
  Top Layer w10: U1.52 2118.23,4276.73 2152.41,4276.73 v1(2153.54,4275.59)
  Bottom Layer w10: v1(2153.54,4275.59) 2191.93,4313.98 2268.7,4313.98 2488.19,4094.49 2653.54,4094.49 2937.01,4377.95 2937.01,4457.43 2929.13,4465.31 R27.1
DDM: R31.2 U1.56 | length 662.3
  Top Layer w10: v1(1625.98,4417.32) 1629.92,4421.26 1858.27,4421.26 1881.89,4397.64 1976.38,4397.64 2007.87,4366.14 2007.87,4275.73 U1.56
  Bottom Layer w10: R31.2@1525.59,4377.95 1598.43,4377.95 1625.98,4405.51 v1(1625.98,4417.32)
DDP: R32.2 U1.57 | length 678.7
  Top Layer w10: v1(1586.61,4409.45) 1602.36,4393.7 1850.39,4393.7 1870.08,4374.02 1964.57,4374.02 1988.19,4350.39 1988.19,4267.58 U1.57
  Bottom Layer w10: R32.2 1565.94,4478.35 1586.61,4457.68 v1(1586.61,4409.45)
ERASE: ERASE.2 R2.2 U1.55 | length 475.1
  Top Layer w10: U1.55 2102.78,4208.66 2157.48,4208.66 2177.17,4228.35 2177.17,4342.52 2100.39,4419.29 R2.2 2098.42,4485.24 ERASE.2
GND: ADC.2 C1.1 C2.1 C3.1 C4.1 C5.1 C6.1 C7.1 C8.1 C9.1 C10.1 C11.1 C12.1 C13.1 C14.1 C15.1 C16.1 C17.1 C18.1 C19.1 C20.1 C21.1 C22.1 C24.1 C25.1 C26.1 C28.1 C31.1 C32.1 C34.1 C35.1 C39.1 GPIO.1 GPIO.4 GPIO.7 GPIO.10 GPIO.13 GPIO.16 GPIO.19 GPS.4 JTAG.7 L3.1 L4.1 microSD.5 MOTORS.1 MOTORS.4 MOTORS.7 MOTORS.10 R1.1 R2.1 R8.1 R25.1 R29.2 R30.2 R35.1 SW1.2 U1.2 U1.3 U1.4 U1.5 U1.17 U1.46 U1.50 U1.60 U2.1 U3.1 U3.9 U3.11 U5.1 U5.2 U5.3 U5.4 USB.5 X1.2 X1.4 XBEE.4 | length 1294.1
  Top Layer w10: v1(2196.85,3877.95) 2196.85,3864.04 U1.17 ; L4.1@2708.66,4074.8 2708.66,4104.33 2739.17,4134.84 2880.91,4134.84 2911.42,4104.33 U3.1 ; C39.1@2757.87,3852.36 C28.1 C24.1@2877.95,3852.36 ; C24.1 2957.68,3850.39 3038.46,3931.18 3038.46,3975.47 U3.11 3040.35,4000 3031.5,4008.86 3010.83,4008.86 3000.98,3999.02 U3.9
  Top Layer w15: C9.1 1730.31,4033.46 C18.1 C19.1 ; X1.4 1793.31,4322.83 1858.27,4257.87 1858.27,4255.91 X1.2
  Top Layer w25: C26.1 v3(1663.39,3751.97)
  Bottom Layer w15: R29.2 1544.29,4429.13 v1(1557.09,4441.93) ; C7.1 C1.1 ; C3.1 C5.1
  other v1: 1224.41,3200.79 1224.41,3275.59 1224.41,3354.33 1901.57,3370.08 2106.3,3370.08 2413.39,3370.08 2622.05,3370.08 2381.89,3523.62 2381.89,3582.68 1948.82,3665.35 2586.61,3665.35 2090.55,3708.66 2137.8,3751.97 2192.91,3759.84 2078.74,3767.72 2814.96,3771.65 2169.29,3795.28 2771.65,3795.28 1933.07,3826.77 1917.32,3952.76 1874.02,3960.63 1877.95,4000 2566.93,4003.94 2688.98,4019.68 2326.77,4027.56 2169.29,4098.43 1562.99,4102.36 2027.56,4106.3 1240.16,4125.98 2330.71,4161.42 2539.37,4169.29 1240.16,4200.79 1562.99,4220.47 2677.17,4224.41 1240.16,4263.78 2476.38,4287.4 1716.54,4299.21 2657.48,4346.46 2728.35,4433.07 2814.96,4440.94 1629.92,4488.19 1732.28,4488.19 2795.28,4500 2964.57,4566.93 1629.92,4570.87 1732.28,4582.68 2421.26,4582.68 2472.44,4582.68 1783.46,4700.79 2114.17,4700.79 1255.91,4759.84 3271.65,4783.46 1255.91,4814.96 1255.91,4870.08 1661.42,4870.08 2889.76,4870.08 2988.19,4870.08 3090.55,4870.08 3181.1,4870.08 3271.65,4870.08
  other v2: 2464.57,4803.15
IN1: R12.1 U1.19 | length 555.5
  Top Layer w10: R12.1 2000,3661.42 2110.24,3661.42 2161.42,3712.6 2232.28,3712.6 2287.4,3767.72 2287.4,3829.17 U1.19
IN2: R16.1 U1.20 | length 531.4
  Top Layer w10: R16.1 2045.28,3637.8 2118.11,3637.8 2169.29,3688.98 2241.5,3688.98 2308.43,3755.91 2308.43,3835.98 U1.20
IN3: R18.1 U1.26 | length 628.1
  Top Layer w10: R18.1 2090.55,3614.17 2125.98,3614.17 2177.17,3665.35 2251.97,3665.35 2425.2,3838.58 2425.2,3886.25 U1.26
IN4: R19.1 U1.29 | length 652.1
  Top Layer w10: R19.1 2187.01,3641.73 2259.84,3641.73 2472.44,3854.33 2472.44,3940.94 2456.69,3956.69 2438.27,3956.69 U1.29
IN5: R20.1 U1.30 | length 625.9
  Top Layer w10: R20.1 2232.28,3618.11 2267.72,3618.11 2492.13,3842.52 2492.13,3948.82 2464.57,3976.38 2446.42,3976.38 U1.30
IN6: R22.1 U1.31 | length 600.9
  Top Layer w10: R22.1 2511.81,3828.74 2511.81,3956.69 2476.22,3992.28 2458.35,3992.28 U1.31
IN7: R23.1 U1.37 | length 956.1
  Top Layer w10: R23.1@2322.83,3570.87 2322.83,3598.43 v1(2417.32,3692.91) ; U1.37 2361.22,4163.39 2361.22,4126.97 2397.64,4090.55 2437.01,4090.55 v1@2523.62,4003.94
  Bottom Layer w10: v1(2417.32,3692.91) 2372.05,3738.19 2352.36,3738.19 2299.21,3791.34 2299.21,3838.58 2464.57,4003.94 v1(2531.5,4003.94)
LED1: R10.1 U1.48 | length 358.9
  Top Layer w10: U1.48 2282.27,4390.67 2295.2,4390.67 2312.99,4408.46 2312.99,4448.82 2298.23,4463.58 R10.1
LED2: R11.1 U1.47 | length 395.3
  Top Layer w10: U1.47 2289.52,4370.08 2305.12,4370.08 2338.58,4403.54 2338.58,4461.61 2324.8,4475.39 2324.8,4620.08 R11.1
MISO: R26.7 R27.4 R28.6 U1.27 | length 1328.4
  Top Layer w10: U1.27 2445.58,3893.7 v1(2448.82,3893.7) ; v1(2568.9,3773.62) 2604.33,3809.06 2604.33,3864.17 2588.58,3879.92 2559.38,3879.92 2550.2,3889.1 2550.2,3941.93 2590.55,3982.28 v1(2590.55,4165.35)
  Bottom Layer w10: v1(2448.82,3893.7) v1(2568.9,3773.62) 2612.2,3773.62 2625.98,3787.4 R26.7@2645.67,3787.4 ; v1(2590.55,4165.35) 2590.55,4240.13 2637.82,4287.4 2751.97,4287.4 2846.46,4381.89 2846.46,4456.45 2834.65,4468.26 R27.4
MOSI: R26.6 R27.2 R28.7 U1.22 | length 1457.1
  Top Layer w10: U1.22 2304.75,3894.04 2346.46,3852.32 2346.46,3850.39 2347.37,3849.48 2347.37,3847.37 2362.2,3832.54 v1(2362.2,3830.71) ; v1(2568.9,3730.32) 2635.83,3797.24 2635.83,3864.91 2650.84,3879.92 2682.09,3879.92 2692.91,3890.75 2692.91,3933.07 2614.17,4011.81 2614.17,4129.92 v1(2625.98,4141.73)
  Bottom Layer w10: v1(2362.2,3830.71) 2480.32,3712.6 2551.18,3712.6 v1(2568.9,3730.32) 2588.58,3730.32 2614.17,3755.91 R26.6@2645.67,3755.91 ; v1(2625.98,4141.73) 2669.29,4141.73 2905.51,4377.95 2905.51,4458.42 2897.64,4466.29 R27.2
NetC18_2: C18.2 R3.1 | length 59.1
  Top Layer w10: C18.2@1675.2,4043.31 R3.1@1675.2,4102.36
NetC21_2: C21.2 J1.1 L2.2 | length 135.1
  Top Layer w25: C21.2 L2.2 ; C21.2@1487.2,3938.98 J1.1 J1.1@1564.96,3936.02
NetC24_2: C24.2 U3.10 | length 189
  Top Layer w10: C24.2@2877.95,3907.48 2980.32,3907.48 3020.67,3947.83 U3.10
NetC25_2: C25.2 U3.20 | length 195.5
  Top Layer w10: C25.2 3007.87,4212.6 3040.35,4180.12 U3.20
NetC36_2: C36.2 U8.5 | length 65.9
  Top Layer w20: U8.5 C36.2@3021.65,3708.66
NetD1_2: D1.2 R1.2 | length 82
  Top Layer w10: D1.2 1316.93,3210.63 R1.2
NetD2_2: D2.2 R10.2 | length 70.4
  Top Layer w10: D2.2 2263.78,4746.06 R10.2
NetD3_2: D3.2 R11.2 | length 55.1
  Top Layer w10: R11.2 D3.2
NetD4_1: D4.1 L1.2 R34.1 | length 231.5
  Bottom Layer w25: R34.1 1468.51,4255.9 D4.1 1523.62,4255.91 L1.2
NetGPIO_3: GPIO.3 R12.2 | length 197.8
  Top Layer w20: GPIO.3 1849.21,3513.78 R12.2@1909.45,3513.78
NetGPIO_6: GPIO.6 R16.2 | length 166.7
  Top Layer w20: GPIO.6 1909.84,3474.41 1938.98,3474.41 R16.2@1978.35,3513.78
NetGPIO_9: GPIO.9 R18.2 | length 134.7
  Top Layer w20: GPIO.9 R18.2@2047.24,3511.81
NetGPIO_12: GPIO.12 R19.2 | length 125.8
  Top Layer w20: GPIO.12 2116.14,3480.71 R19.2
NetGPIO_15: GPIO.15 R20.2 | length 112.9
  Top Layer w20: GPIO.15 2185.04,3449.61 R20.2
NetGPIO_18: GPIO.18 R22.2 | length 97.2
  Top Layer w20: GPIO.18 R22.2@2251.97,3513.78
NetGPIO_21: GPIO.21 R23.2 | length 111.3
  Top Layer w20: R23.2@2322.83,3515.75 2322.83,3445.67 GPIO.21
NetGPS_1: GPS.1 L2.1 | length 181.2
  Top Layer w25: GPS.1 1393.7,3992.13 1443.9,4042.32 L2.1
NetL1_1: L1.1 USB.1 | length 205.5
  Bottom Layer w15: USB.1 1407.48,4437.24 1407.48,4360.24 1437.01,4330.71 L1.1
NetL5_1: L5.1 XBEE.1 | length 228.7
  Top Layer w10: L5.1 2011.81,4547.24 2055.12,4590.55 v1(2055.12,4641.73)
  Bottom Layer w10: XBEE.1 2021.65,4675.2 v1(2055.12,4641.73)
NetmicroSD_1: microSD.1 R27.8 | length 476.4
  Bottom Layer w10: microSD.1@2629.92,4866.14 2629.92,4830.71 2677.17,4783.46 2736.22,4783.46 2929.13,4590.55 R27.8@2929.13,4548.23
NetmicroSD_2: microSD.2 R27.7 | length 487.1
  Bottom Layer w10: microSD.2@2586.61,4866.14 2586.61,4824.8 2651.57,4759.84 2720.47,4759.84 2897.64,4582.68 R27.7@2897.64,4548.23
NetmicroSD_4: microSD.4 R27.6 | length 555.4
  Bottom Layer w10: microSD.4@2500,4866.14 2500,4793.31 2559.06,4734.25 2706.69,4734.25 2865.65,4575.3 ; R27.6@2866.14,4548.23 2866.14,4574.8
NetmicroSD_6: microSD.6 R27.5 | length 605.4
  Bottom Layer w10: microSD.6@2413.39,4866.14 2413.39,4795.28 2500,4708.66 2692.91,4708.66 2833.17,4568.41 2833.17,4549.7 R27.5@2834.65,4548.23
NetMOTORS_3: MOTORS.3 R9.2 | length 112.3
  Top Layer w20: R9.2 2440.94,3448.03 MOTORS.3
NetMOTORS_6: MOTORS.6 R13.2 | length 125.1
  Top Layer w20: R13.2 2509.84,3479.13 MOTORS.6
NetMOTORS_9: MOTORS.9 R17.2 | length 138
  Top Layer w20: R17.2 2578.74,3510.24 MOTORS.9
NetMOTORS_12: MOTORS.12 R21.2 | length 165.9
  Top Layer w20: R21.2 2673.23,3515.75 MOTORS.12
NetQ1_1: Q1.1 R33.1 | length 325.6
  Bottom Layer w10: Q1.1 1331.69,4796.26 1523.62,4604.33 R33.1
NetR26_1: R26.1 U10.5 | length 784.2
  Top Layer w10: v1(3137.8,3472.44) 3175.2,3435.04 U10.5
  Bottom Layer w10: R26.1 2712.6,3818.9 2787.4,3744.09 3086.61,3744.09 3137.8,3692.91 v1(3137.8,3472.44)
NetR26_2: R26.2 U10.6 | length 786.9
  Top Layer w10: v1(3129.92,3437.01) 3181.1,3385.83 U10.6
  Bottom Layer w10: R26.2 2711.61,3787.4 2782.48,3716.54 3062.99,3716.54 3106.3,3673.23 3106.3,3460.63 v1(3129.92,3437.01)
NetR26_3: R26.3 U10.7 | length 789.7
  Top Layer w10: v1(3133.86,3389.76) 3187.01,3336.61 U10.7
  Bottom Layer w10: R26.3 2710.63,3755.91 2781.5,3685.04 3043.31,3685.04 3074.8,3653.54 3074.8,3448.82 v1(3133.86,3389.76)
NetR26_4: R26.4 U10.8 | length 792.4
  Top Layer w10: v1(3129.92,3350.39) U10.8
  Bottom Layer w10: R26.4 2706.69,3724.41 2769.68,3661.42 3015.75,3661.42 3043.31,3633.86 3043.31,3437.01 v1(3129.92,3350.39)
NetR29_1: R29.1 R31.1 USB.2 | length 190.3
  Bottom Layer w10: USB.2 1403.54,4501.97 1417.32,4488.19 1417.32,4468.5 1456.69,4429.13 R29.1 R31.1
NetR30_1: R30.1 R32.1 R33.2 USB.3 | length 197.8
  Bottom Layer w10: USB.3 R30.1 ; R32.1 R30.1 ; R33.2 R30.1
NRST: C10.2 JTAG.1 R4.1 SW1.3 U1.39 | length 1236.6
  Top Layer w10: U1.39 2385.26,4243.11 2530.51,4243.11 2551.18,4263.78 2551.18,4366.14 2610.24,4425.2 2677.17,4425.2 2726.38,4474.41 SW1.3 3055.12,4602.36 3068.9,4588.58 C10.2 ; R4.1 C10.2 ; JTAG.1@3147.64,4665.35 JTAG.1 3159.45,4657.48 C10.2
PLLRC: C17.2 R3.2 U1.63 | length 378.6
  Top Layer w10: R3.2@1730.32,4102.36 C17.2@1730.32,4161.42 ; R3.2 1765.75,4078.74 1942.91,4078.74 1968.5,4104.33 1968.5,4120.23 U1.63
PULLUP: Q1.3 U1.10 | length 1569.2
  Top Layer w10: v1(2000,3862.2) 2004.36,3862.2 U1.10
  Bottom Layer w10: Q1.3 1604.33,4860.24 1692.91,4771.65 1692.91,4437.01 1602.36,4346.46 1602.36,4196.85 1870.08,3929.13 1992.13,3929.13 2011.81,3909.45 2011.81,3874.02 v1(2000,3862.2)
PWM0: R9.1 U1.15 | length 515.5
  Top Layer w10: U1.15 2147.49,3866.14 2169.29,3866.14 2188.98,3846.46 2188.98,3826.77 v1(2244.09,3771.65) ; v1(2438.98,3659.45) 2438.98,3572.83 R9.1
  Bottom Layer w10: v1(2244.09,3771.65) 2281.5,3771.65 2393.7,3659.45 v1(2438.98,3659.45)
PWM1: R13.1 U1.23 | length 486
  Top Layer w10: U1.23 2359.82,3868.11 v1(2367.13,3868.11) ; v1(2506.38,3779.53) 2503.94,3779.53 2476.38,3751.97 2476.38,3604.33 R13.1
  Bottom Layer w10: v1(2367.13,3868.11) 2376.97,3877.95 2407.95,3877.95 v1(2506.38,3779.53)
PWM2: R17.1 U1.25 | length 468.2
  Top Layer w10: U1.25 2397.64,3885.97 v1(2397.64,3850.39) ; v1(2503.94,3744.09) 2503.94,3635.83 2568.9,3570.87 R17.1
  Bottom Layer w10: v1(2397.64,3850.39) v1(2503.94,3744.09)
PWM3: R21.1 U1.32 | length 566.4
  Top Layer w10: U1.32 2466.67,4011.81 2488.19,4011.81 2531.5,3968.5 2531.5,3677.17 2637.8,3570.87 R21.1
RXD0: U1.35 XBEE.2 | length 1015.4
  Top Layer w10: U1.35 2454.29,4200.79 2496.06,4200.79 v1(2507.87,4188.98)
  Bottom Layer w10: XBEE.2 1972.44,4448.82 2027.56,4393.7 2303.15,4393.7 v1(2507.87,4188.98)
RXD1: GPS.3 U1.11 | length 925.1
  Top Layer w10: v4(1332.68,3824.8) GPS.3 ; v1(1966.54,3769.68) 2023.62,3826.77 2023.62,3853.63 U1.11
  Bottom Layer w10: v4(1332.68,3824.8) 1353.35,3804.13 1461.61,3804.13 1496.06,3769.68 1555.12,3769.68 1604.33,3818.9 1858.27,3818.9 1907.48,3769.68 v1(1966.54,3769.68)
SCL: COMPASS.3 R14.2 U1.36 U3.23 U5.6 | length 1787.6
  Top Layer w10: COMPASS.3 1974.41,4679.13 v1(2007.87,4645.67) ; U1.36 2446.14,4220.47 2566.93,4220.47 R14.2 2578.74,4293.24 2577.56,4294.42 U5.6 v1@2577.56,4347.64 ; v1(2578.74,4346.46) 2578.74,4358.27 2622.05,4401.57 2681.1,4401.57 2740.16,4342.52 2740.16,4248.03 2811.02,4177.17 2960.63,4177.17 2979.41,4158.39 2979.41,4134.76 U3.23
  Bottom Layer w10: v1(2007.87,4645.67) 2035.43,4618.11 2035.43,4468.5 2060.04,4443.9 2356.3,4443.9 2434.06,4366.14 2559.06,4366.14 v1(2578.74,4346.46)
SDA: COMPASS.2 R15.2 U1.43 U3.24 U5.5 | length 1770.1
  Top Layer w10: COMPASS.2 1925.2,4669.29 1996.06,4598.43 v1(2003.94,4598.43) ; U1.43 2404.81,4374.01 R15.2 2480.32,4374.01 v1@2519.68,4334.65 ; v1(2629.92,4370.08) 2637.8,4377.95 2673.23,4377.95 2712.6,4338.58 2712.6,4240.16 2797.24,4155.51 2891.73,4155.51 2914.37,4132.87 U3.24
  Bottom Layer w10: v1(2003.94,4598.43) 1996.06,4590.55 1996.06,4465.55 2041.34,4420.28 2331.69,4420.28 2421.26,4330.71 v1(2523.62,4330.71) 2533.46,4320.87 2598.43,4320.87 2629.92,4352.36 v1@2629.92,4365.24
SPCK: R26.5 R27.3 R28.8 U1.21 | length 1521.1
  Top Layer w10: U1.21 2334.65,3837.6 2334.65,3799.21 v1(2338.58,3795.28) ; v1(2608.27,3700.79) 2608.27,3730.32 2667.32,3789.37 2667.32,3856.3 2698.82,3856.3 2712.6,3870.08 2712.6,3952.76 2637.8,4027.56 2637.8,4106.3 2657.48,4125.98 2657.48,4149.61 v1(2625.98,4181.1)
  Bottom Layer w10: v1(2338.58,3795.28) 2356.3,3795.28 2466.54,3685.04 2562.99,3685.04 2578.74,3700.79 v1(2608.27,3700.79) 2631.89,3724.41 R26.5@2645.67,3724.41 ; v1(2625.98,4181.1) 2677.17,4181.1 2874.02,4377.95 2874.02,4459.4 2866.14,4467.27 R27.3
TCK: JTAG.4 R7.1 U1.53 | length 1455
  Top Layer w10: U1.53 2106.3,4260.82 2128.94,4260.82 v1@2145.67,4244.09 ; R7.1 3124.8,4330.71 JTAG.4
  Bottom Layer w10: v1(2149.61,4236.22) 2196.85,4283.46 2263.78,4283.46 2507.87,4039.37 2667.32,4039.37 2993.31,4365.35 JTAG.4
TDI: JTAG.2 R5.1 U1.33 | length 1167.3
  Top Layer w10: U1.33 2443.94,4115.11 2492.13,4066.93 v1(2519.68,4066.93) ; R5.1 3159.45,4539.37 JTAG.2
  Bottom Layer w10: v1(2519.68,4066.93) 2523.62,4062.99 2657.48,4062.99 2972.44,4377.95 2972.44,4460.63 3077.17,4565.35 JTAG.2
TDO: JTAG.8 U1.49 | length 1499.2
  Top Layer w10: v1(2068.9,4474.41) 2062.99,4468.5 2062.99,4401.57 2078.74,4385.83 2092.65,4385.83 U1.49 ; v1(2759.84,4393.7) 2767.72,4393.7 2893.7,4267.72 3181.1,4267.72 3259.45,4346.06 JTAG.8
  Bottom Layer w10: v1(2068.9,4474.41) 2076.77,4466.54 2370.08,4466.54 2427.97,4408.65 2741.29,4408.65 2756.23,4393.7 v1(2759.84,4393.7)
TMS: JTAG.3 R6.1 U1.51 | length 1874.8
  Top Layer w10: v1(2035.43,4338.58) 2039.37,4342.52 2080.28,4342.52 U1.51 ; v1(2807.09,4393.7) 2909.45,4291.34 3165.35,4291.34 3208.66,4334.65 3208.66,4416.14 JTAG.3 3083.86,4389.76 R6.1
  Bottom Layer w10: v1(2035.43,4338.58) 2275.59,4338.58 2496.06,4118.11 2543.31,4118.11 2562.99,4137.8 2562.99,4251.97 2622.05,4311.02 2744.09,4311.02 2807.09,4374.02 v1(2807.09,4393.7)
TST: R8.2 TST.2 U1.40 | length 462.7
  Top Layer w10: TST.2@2224.9,4505.41 2216.53,4497.05 R8.2 2214.57,4419.29 2194.88,4399.61 2194.88,4261.81 2263.78,4192.91 2307.23,4192.91 U1.40 ; TST.2@2225.89,4506.4 TST.2@2231.3,4511.81 ; TST.2@2226.38,4503.94 TST.2
TXD0: U1.34 XBEE.3 | length 1062.4
  Top Layer w10: U1.34 2458.51,4177.17 2476.38,4177.17 v1(2507.87,4145.67)
  Bottom Layer w10: XBEE.3 1923.23,4466.54 2023.62,4366.14 2287.4,4366.14 v1(2507.87,4145.67)
TXD1: GPS.2 U1.14 | length 1071
  Top Layer w10: v4(1289.37,3828.74) 1334.65,3874.02 GPS.2 ; v1(2000,3755.91) 2009.41,3755.91 U1.14
  Bottom Layer w10: v4(1289.37,3828.74) 1289.37,3818.9 1328.74,3779.53 1446.85,3779.53 1486.22,3740.16 1574.8,3740.16 1624.02,3789.37 1848.43,3789.37 1897.64,3740.16 1984.25,3740.16 v1(2000,3755.91)
"VBUS MON": R34.2 R35.2 U1.9 | length 852.8
  Top Layer w10: v1(1976.38,3897.64) 2011.95,3897.64 U1.9
  Bottom Layer w10: R35.2@1320.87,4200.79 R35.2 R34.2 1417.32,4173.23 1594.49,4173.23 1870.08,3897.64 v1(1976.38,3897.64)
VDDOUT: C4.2 C5.2 C6.2 C13.2 C14.2 C20.2 U1.8 U1.12 U1.24 U1.54 U1.64 | length 1634.7
  Top Layer w10: v1(1629.92,4216.54) C13.2@1665.91,4252.52 ; C20.2 v1(1901.57,4114.17) 1905.56,4114.17 U1.64 ; U1.8 2058.91,3972.44 v1(2080.51,3972.44) 2125.39,3927.56 ; U1.54 2103.06,4236.22 v1(2114.17,4236.22) ; U1.12 2125.39,3927.56 ; v1@2271.65,3988.19 2216.14,3988.19 v1(2155.51,3927.56) 2125.39,3927.56 ; v1(2273.43,3986.42) 2273.43,3982.34 U1.24
  Bottom Layer w10: v1(1629.92,4216.54) 1732.28,4114.17 v1(1901.57,4114.17) 1944.88,4070.87 1992.13,4070.87 ; v1(2080.51,3972.44) 2080.51,4010.04 C14.2@2088.38,4017.91 ; C14.2 C14.2@2088.38,4017.91 ; C6.2@2189.37,4208.66 2133.86,4208.66 2114.17,4228.35 v1(2114.17,4236.22) 2098.43,4236.22 1992.13,4129.92 1992.13,4074.8 2049.02,4017.91 C14.2@2088.38,4017.91 ; v1(2273.43,3986.42) C5.2
VIN: GPIO.2 GPIO.5 GPIO.8 GPIO.11 GPIO.14 GPIO.17 GPIO.20 L7.1 L8.1 MOTORS.2 MOTORS.5 MOTORS.8 MOTORS.11 | length 1594.3
  Top Layer w35: MOTORS.11 MOTORS.11@2775.2,3316.54
  Top Layer w40: L7.1 1625.98,3622.05 1625.98,3482.28 ; MOTORS.11@2775.2,3316.54 2834.65,3375.98 2834.65,3446.85 L8.1
  Top Layer w45: 1625.98,3482.28 1692.91,3415.35 1692.91,3375.59 GPIO.2 GPIO.5 GPIO.8 GPIO.11 GPIO.14 GPIO.17 GPIO.20 MOTORS.2 MOTORS.5 MOTORS.8 MOTORS.11
XIN: C15.2 U1.62 X1.1 | length 234.2
  Top Layer w10: X1.1@1787.4,4255.91 1848.43,4194.88 C15.2 1879.92,4173.23 1899.61,4192.91 1923.66,4192.91 U1.62
XOUT: C16.2 U1.61 X1.3 | length 219
  Top Layer w10: X1.3@1874.02,4322.83 1885.83,4322.83 1929.13,4279.53 1952.76,4279.53 1937.01,4263.78 1937.01,4207.4 U1.61
pads on no net: ADC.0 ADC.5 COMPASS.0 COMPASS.1 COMPASS.4 COMPASS.5 GPS.0 GPS.5 GPS.7 JTAG.6 microSD.7 SW1.1 SW1.4 U1.13 U1.16 U1.38 U1.41 U1.42 U1.44 U3.2 U3.4 U3.5 U3.6 U3.7 U3.12 U3.14 U3.16 U3.19 U3.21 U3.22 U5.7 U10.4 USB.4 USB.6 USB.18 USB.19 XBEE.0 XBEE.5

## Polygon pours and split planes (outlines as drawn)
GND on Top Layer "Bottom Layer-No Net" (solid, remove dead copper, pour order 10): 1181.1,4921.26 3346.46,4921.26 3346.46,3149.61 1181.1,3149.61
A3V3 on Top Layer "Bottom Layer-No Net" (solid, remove dead copper, pour order 18): 2913.39,3651.57 3021.65,3651.57 3031.5,3651.57 3051.18,3632.78 3051.18,3463.67 3031.5,3444.88 2942.91,3444.88 2933.07,3444.88 2913.39,3463.67
3.3V on Top Layer "Bottom Layer-No Net" (solid, remove dead copper, pour order 16): 1722.44,4005.91 1722.44,3710.63 1653.54,3641.73 1653.54,3543.31 1653.54,3533.46 1712.6,3474.41 1909.84,3474.41 1909.84,3710.24 1850.39,3769.68 1850.39,3986.22 1830.71,4005.91
5VB on Top Layer "Bottom Layer-No Net" (solid, remove dead copper, pour order 14): 1712.6,3710.63 1673.23,3671.26 1496.06,3671.26 1496.06,3838.58 1496.06,3868.11 1535.43,3907.48 1712.6,3907.48
5VA on Top Layer "Bottom Layer-No Net" (solid, remove dead copper, pour order 6): 2893.7,3503.94 2893.7,3730.32 2814.96,3730.32 2814.96,3654.86 2785.43,3626.56 2726.38,3626.56 2696.85,3654.86 2608.27,3654.86 2608.27,3503.94
AGND on Top Layer "Bottom Layer-No Net" (solid, remove dead copper, pour order 9): 3346.46,3149.61 3070.87,3149.61 2858.27,3149.61 2858.27,3413.39 2905.51,3460.63 2905.51,3728.35 2818.9,3814.96 2818.9,3885.83 2818.9,3907.48 2818.9,3913.39 2783.46,3948.82 2736.22,3996.06 2736.22,4078.74 2913.39,4255.91 3346.46,4255.91
GND on Bottom Layer "Bottom Layer-No Net" (solid, remove dead copper, pour order 12): 1181.1,4921.26 3346.46,4921.26 3346.46,3149.61 1186.02,3149.61 1181.1,3154.53
AGND on Bottom Layer "Bottom Layer-No Net" (solid, remove dead copper, pour order 11): 2913.39,4255.91 2736.22,4078.74 2736.22,3996.06 2803.15,3929.13 2814.96,3917.32 2818.9,3913.39 2818.9,3814.96 2838.58,3795.28 2905.51,3728.35 2905.51,3645.67 2905.51,3460.63 2858.27,3413.39 2858.27,3409.45 2858.27,3149.61 3346.46,3149.61 3346.46,4255.9 3346.46,4255.91
no net on VCC (split plane): 3100.34,3966.59 2923.28,3966.59 2923.28,4143.65 3100.34,4143.65
A3V3 on VCC (split plane): 3326.36,3529.58 3131.89,3529.58 3130.35,3529.38 3128.91,3528.78 3127.68,3527.83 3123.47,3523.62 3075.79,3523.62 3075.79,3475.94 3067.64,3467.79 3066.69,3466.56 3066.1,3465.12 3065.89,3463.58 3065.89,3169.7 2865.21,3169.7 2865.21,3411.13 2878.3,3424.22 2879.21,3424.92 2911.69,3457.4 2912.64,3458.64 2912.89,3459.23 2913.23,3460.07 2913.44,3461.61 2913.44,3726.38 2913.23,3727.92 2912.81,3728.94 2912.64,3729.36 2911.69,3730.59 2823.87,3818.41 2823.87,3914.37 2823.67,3915.91 2823.07,3917.35 2822.13,3918.58 2741.19,3999.51 2741.19,4075.29 2914.87,4248.96 3326.36,4248.96
3.3V on VCC (split plane): 3326.36,4260.88 2912.4,4260.88 2910.86,4260.67 2909.42,4260.08 2908.19,4259.13 2731.02,4081.97 2730.08,4080.73 2729.48,4079.3 2729.28,4077.76 2729.28,3997.05 2729.48,3995.51 2730.08,3994.07 2731.02,3992.84 2811.96,3911.9 2811.96,3815.94 2812.16,3814.4 2812.75,3812.97 2813.7,3811.73 2901.52,3723.91 2901.52,3464.08 2871.49,3434.04 2870.58,3433.35 2855.04,3417.81 2854.09,3416.58 2853.5,3415.14 2853.3,3413.6 2853.3,3169.7 1201.2,3169.7 1201.2,4901.16 3326.36,4901.16
no net on GND (split plane): 3100.34,3966.59 2923.28,3966.59 2923.28,4143.65 3100.34,4143.65
AGND on GND (split plane): 3326.36,3529.58 3134.84,3529.58 3133.3,3529.38 3132.28,3528.95 3131.86,3528.78 3130.63,3527.83 3124.45,3521.65 3072.83,3521.65 3072.83,3470.04 3066.65,3463.86 3065.71,3462.62 3065.11,3461.19 3064.91,3459.65 3064.91,3169.7 2865.3,3169.7 2865.21,3169.79 2865.21,3411.9 2910.71,3457.4 2911.65,3458.64 2912.25,3460.07 2912.45,3461.61 2912.45,3731.3 2912.25,3732.84 2911.9,3733.68 2911.65,3734.28 2910.71,3735.51 2823.87,3822.35 2823.87,3914.37 2823.67,3915.91 2823.07,3917.35 2822.13,3918.58 2740.21,4000.5 2740.21,4075.29 2913.88,4248.96 3326.36,4248.96
GND on GND (split plane): 3326.36,4260.88 2911.42,4260.88 2909.88,4260.67 2908.44,4260.08 2907.21,4259.13 2730.04,4081.97 2729.09,4080.73 2728.5,4079.3 2728.3,4077.76 2728.3,3998.03 2728.5,3996.49 2729.09,3995.05 2730.04,3993.82 2811.96,3911.9 2811.96,3819.88 2812.16,3818.34 2812.75,3816.9 2813.7,3815.67 2900.54,3728.83 2900.54,3464.08 2855.04,3418.58 2854.09,3417.35 2853.5,3415.91 2853.3,3414.37 2853.3,3169.7 1201.2,3169.7 1201.2,4901.16 3326.36,4901.16

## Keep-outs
Keep-Out Layer:
  pour cut-out: 2944.88,4122.05 3078.74,4122.05 3078.74,3988.19 2944.88,3988.19
  pour cut-out: 3346.46,3149.61 3346.46,3519.68 3137.8,3519.68 3070.87,3460.63 3070.87,3149.61

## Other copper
VCC (plane layer: these items are gaps in the copper):
  rectangle: 2935.04,3982.28 3085.63,4131.89
  rectangle: 3075.79,3163.39 3335.63,3523.62
  lines w11.81: 2859.25,3149.61 2859.25,3413.6 2874.79,3429.13 2875,3429.13 2907.48,3461.61 2907.48,3726.38 2817.91,3815.94 2817.91,3914.37 2735.24,3997.05 2735.24,4077.76 2912.4,4254.92 3346.46,4254.92 ; 3071.85,3149.61 3071.85,3463.58 3131.89,3523.62 3334.65,3523.62 3346.46,3535.43 ; 2917.32,3960.63 2917.32,4149.61 3106.3,4149.61 3106.3,3960.63 2917.32,3960.63
GND (plane layer: these items are gaps in the copper):
  rectangle: 2935.04,3982.28 3085.63,4131.89
  rectangle: 3072.83,3161.42 3332.68,3521.65
  lines w11.81: 3070.87,3150.59 3070.87,3459.65 3134.84,3523.62 3335.63,3523.62 3346.46,3534.45 ; 3346.46,3149.61 2876.97,3149.61 2859.25,3167.32 2859.25,3414.37 2906.5,3461.61 2906.5,3731.3 2817.91,3819.88 2817.91,3914.37 2734.25,3998.03 2734.25,4077.76 2911.42,4254.92 3346.46,4254.92 ; 3346.46,4060.04 3346.46,4070.87 ; 2917.32,3960.63 2917.32,4149.61 3106.3,4149.61 3106.3,3960.63 2917.32,3960.63

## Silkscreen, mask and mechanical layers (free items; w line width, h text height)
Top Overlay:
  lines w10: 1684.02,3333.35 cw(c1574.8,3346.46) 1684.21,3335.05 ; 1684.02,4711.3 cw(c1574.8,4724.41) 1684.21,4713 ; 3061.97,3333.35 cw(c2952.76,3346.46) 3062.16,3335.05 ; 3061.97,4711.3 cw(c2952.76,4724.41) 3062.16,4713
Mechanical 1:
  the board outline again, w11.81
